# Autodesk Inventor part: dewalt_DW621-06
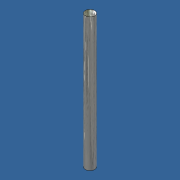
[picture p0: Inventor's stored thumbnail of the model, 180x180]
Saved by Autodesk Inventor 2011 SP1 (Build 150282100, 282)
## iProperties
Created: 2011-02
Part Number: dewalt_DW621-06
Material: 1.0037 St 37-2 / S235JR
Catalog Web Link: www.mittelmeyer.de
Document SubType Name: Modellieren
Designer: TMT
Manufacturer: Standard
Standards Organization: Custom
Density: 1 g/cm^3
Author: TMT
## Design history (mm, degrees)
sketch "Skizze2"
  geometry: C1 r 7 at (0, 0); 1 further point
  constraints: 1 centre point, 1 coincident
  dimensions: "d5" = 14 diameter of C1 (= durchmesser_01)
extrude "Extrusion2" new body sketch "Skizze2" distance "d6" = 200 (= hoehe_01); taper "d7" = 0 deg
node "Volumenkörper1"
node "Volumenkörpern"
node "Oberflächenkörpern"
other parameters: "durchmesser_01" = 14 [user parameter; used in 1 equation term], "hoehe_01" = 200 [user parameter; used in 1 equation term]
